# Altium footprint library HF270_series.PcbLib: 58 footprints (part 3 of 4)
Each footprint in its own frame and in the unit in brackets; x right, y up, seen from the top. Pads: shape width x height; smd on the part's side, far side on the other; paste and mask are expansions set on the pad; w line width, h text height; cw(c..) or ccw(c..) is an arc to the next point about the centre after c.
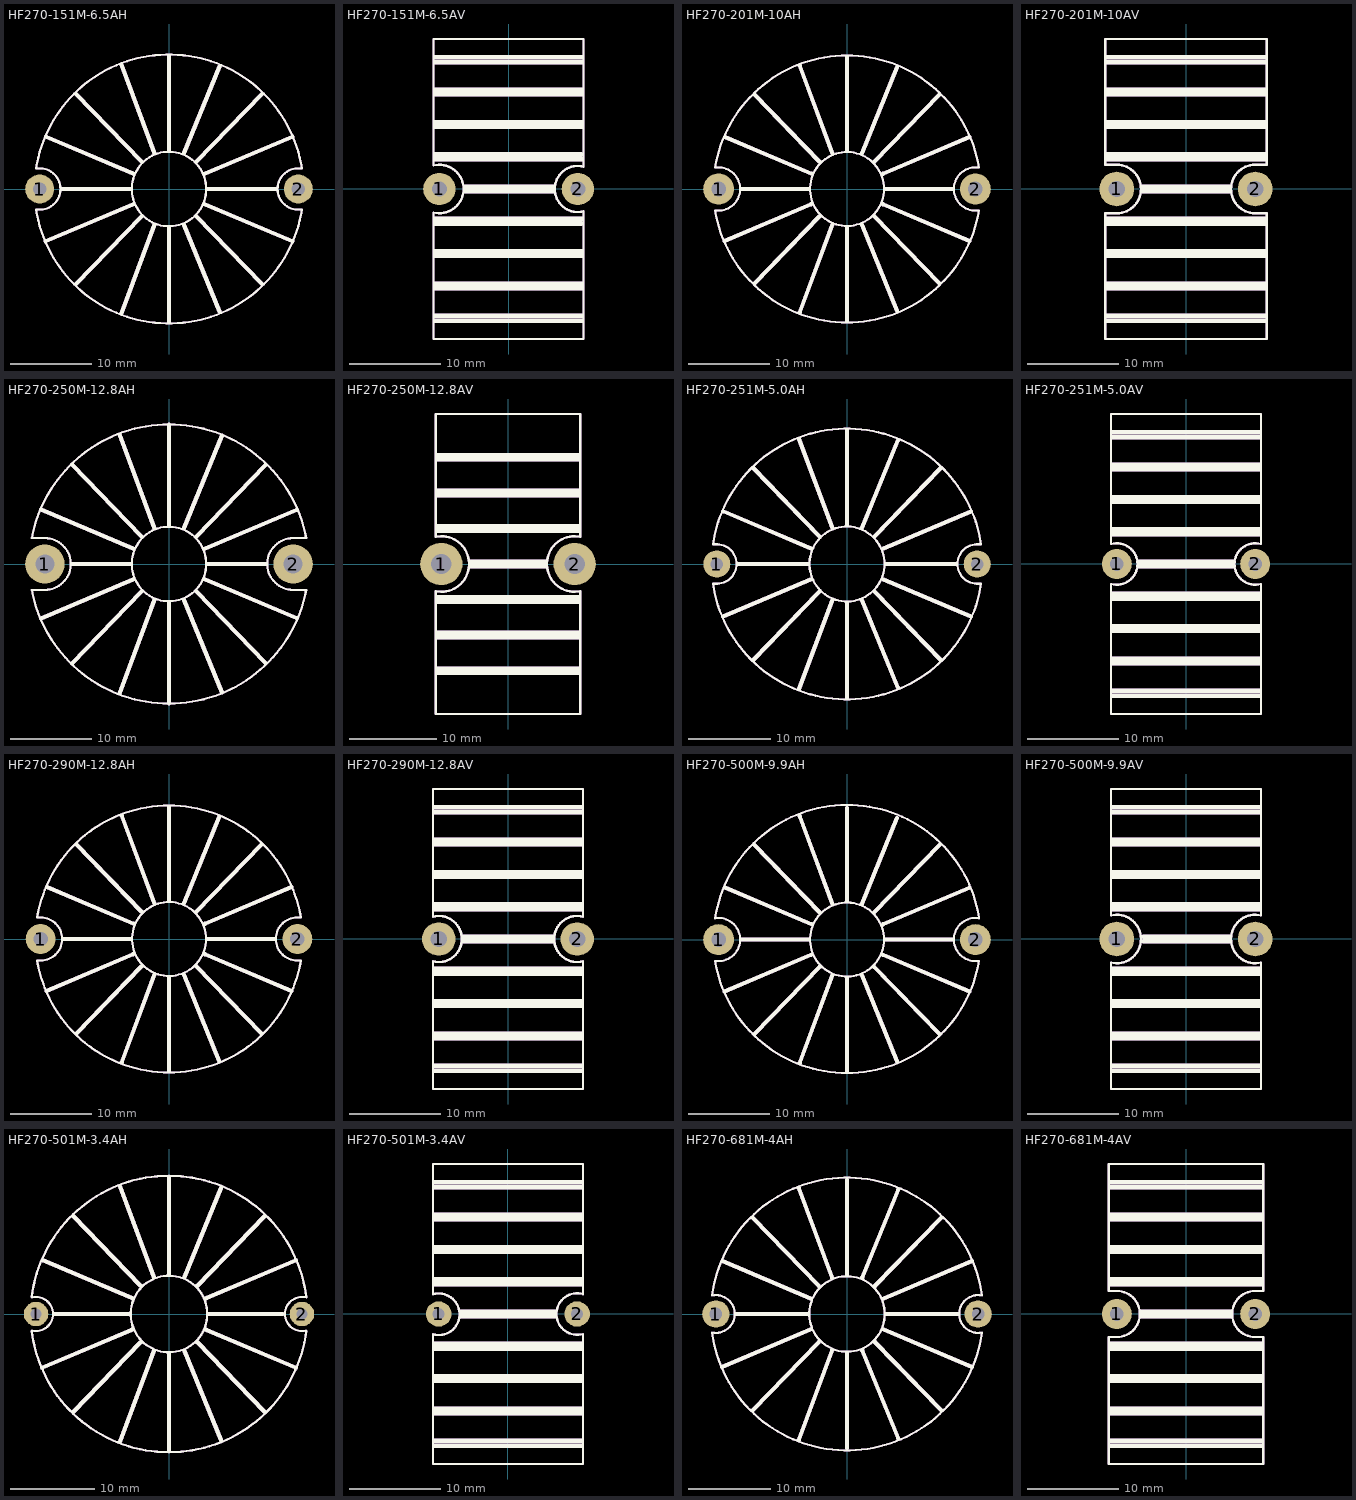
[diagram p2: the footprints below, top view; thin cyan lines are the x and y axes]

## HF270-151M-6.5AH [mil]
pads (2):
  round 140 hole 65: 1(-625,0) 2(625,0)
Top Overlay:
  circle w10: c0,0 r180
  lines w10: -642.5,-98.46 ccw(c0,0) 642.5,-98.46 cw(c625,0) 642.5,98.46 ccw(c0,0) -642.5,98.46 cw(c-625,0) -642.5,-98.46
  lines w19.68: -596.03,-252.56 -175.3,-74.28 ; -593.79,252.95 -173.05,74.68 ; -520,0 -185,0 ; -450,-460 -132.7,-132.43 ; -450,460 -132.7,132.43 ; -230,-600 -70.44,-171.87 ; -230,600 -70.44,171.87 ; 0,-640 0,-185 ; 0,185 0,640 ; 72.46,-173.99 243.97,-592.47 ; 72.46,173.99 243.97,592.47 ; 132.5,-132.5 450,-460 ; 132.5,132.5 450,460 ; 175.3,-74.28 596.03,-252.56 ; 175.3,74.28 596.03,252.56 ; 185,0 520,0
Mechanical 29:
  circle w10: c0,0 r180
  lines w10: -642.5,-98.46 ccw(c0,0) 642.5,-98.46 cw(c625,0) 642.5,98.46 ccw(c0,0) -642.5,98.46 cw(c-625,0) -642.5,-98.46
  lines w19.68: -596.03,-252.56 -175.3,-74.28 ; -593.79,252.95 -173.05,74.68 ; -520,0 -185,0 ; -450,-460 -132.7,-132.43 ; -450,460 -132.7,132.43 ; -230,-600 -70.44,-171.87 ; -230,600 -70.44,171.87 ; 0,-640 0,-185 ; 0,185 0,640 ; 72.46,-173.99 243.97,-592.47 ; 72.46,173.99 243.97,592.47 ; 132.5,-132.5 450,-460 ; 132.5,132.5 450,460 ; 175.3,-74.28 596.03,-252.56 ; 175.3,74.28 596.03,252.56 ; 185,0 520,0
  text "'.Designator'" at -290,145.15 h400

## HF270-151M-6.5AV [mil]
pads (2):
  round 140 hole 65: 1(-300,0) 2(300,0)
Top Overlay:
  lines w10: -325,-650 325,-650 325,-96.82 cw(c300,0) 325,96.82 325,650 -325,650 -325,101.98 cw(c-300,0) -325,-101.98 -325,-650
  lines w19.68: -320,-570 320,-570 ; -320,-550 320,-550 ; -320,-430 320,-430 ; -320,-410 320,-410 ; -320,-290 320,-290 ; -320,-270 320,-270 ; -320,-150 315,-150 ; -320,-130 320,-130 ; -320,130 320,130 ; -320,150 315,150 ; -320,270 320,270 ; -320,290 320,290 ; -320,410 320,410 ; -320,430 320,430 ; -320,550 320,550 ; -320,570 320,570 ; -190,-10 195,-10 ; -190,10 195,10
Mechanical 29:
  lines w10: -325,-650 325,-650 325,-96.82 cw(c300,0) 325,96.82 325,650 -325,650 -325,101.98 cw(c-300,0) -325,-101.98 -325,-650
  lines w19.68: -320,-570 320,-570 ; -320,-550 320,-550 ; -320,-430 320,-430 ; -320,-410 320,-410 ; -320,-290 320,-290 ; -320,-270 320,-270 ; -320,-150 315,-150 ; -320,-130 320,-130 ; -320,130 320,130 ; -320,150 315,150 ; -320,270 320,270 ; -320,290 320,290 ; -320,410 320,410 ; -320,430 320,430 ; -320,550 320,550 ; -320,570 320,570 ; -190,-10 195,-10 ; -190,10 195,10
  text "'.Designator'" at -1750,-64.85 h400

## HF270-201M-10AH [mil]
pads (2):
  round 150 hole 71: 1(-625,0) 2(625,0)
Top Overlay:
  circle w10: c0,0 r180
  lines w10: -641.68,-103.67 ccw(c0,0) 641.68,-103.67 cw(c625,0) 641.68,103.67 ccw(c0,0) -641.68,103.67 cw(c-625,0) -641.68,-103.67
  lines w19.68: -596.03,-252.56 -175.3,-74.28 ; -593.79,252.95 -173.05,74.68 ; -515,0 -185,0 ; -450,-460 -132.7,-132.43 ; -450,460 -132.7,132.43 ; -230,-600 -70.44,-171.87 ; -230,600 -70.44,171.87 ; 0,-640 0,-185 ; 0,185 0,640 ; 72.46,-173.99 243.97,-592.47 ; 72.46,173.99 243.97,592.47 ; 132.5,-132.5 450,-460 ; 132.5,132.5 450,460 ; 175.3,-74.28 596.03,-252.56 ; 175.3,74.28 596.03,252.56 ; 185,0 515,0
Mechanical 29:
  circle w10: c0,0 r180
  lines w10: -641.68,-103.67 ccw(c0,0) 641.68,-103.67 cw(c625,0) 641.68,103.67 ccw(c0,0) -641.68,103.67 cw(c-625,0) -641.68,-103.67
  lines w19.68: -596.03,-252.56 -175.3,-74.28 ; -593.79,252.95 -173.05,74.68 ; -515,0 -185,0 ; -450,-460 -132.7,-132.43 ; -450,460 -132.7,132.43 ; -230,-600 -70.44,-171.87 ; -230,600 -70.44,171.87 ; 0,-640 0,-185 ; 0,185 0,640 ; 72.46,-173.99 243.97,-592.47 ; 72.46,173.99 243.97,592.47 ; 132.5,-132.5 450,-460 ; 132.5,132.5 450,460 ; 175.3,-74.28 596.03,-252.56 ; 175.3,74.28 596.03,252.56 ; 185,0 515,0
  text "'.Designator'" at -290,145.15 h400

## HF270-201M-10AV [mil]
pads (2):
  round 150 hole 71: 1(-300,0) 2(300,0)
Top Overlay:
  lines w10: -350,-650 350,-650 350,-105 300,-105 cw(c300,0) 300,105 350,105 350,650 -350,650 -350,105 -300,105 cw(c-300,0) -300,-105 -350,-105 -350,-650
  lines w19.68: -345,-570 345,-570 ; -345,-550 345,-550 ; -345,-430 345,-430 ; -345,-410 345,-410 ; -345,-290 345,-290 ; -345,-270 345,-270 ; -345,-150 345,-150 ; -345,-130 345,-130 ; -345,130 345,130 ; -345,150 345,150 ; -345,270 345,270 ; -345,290 345,290 ; -345,410 345,410 ; -345,430 345,430 ; -345,550 345,550 ; -345,570 345,570 ; -190,-10 190,-10 ; -190,10 190,10
Mechanical 29:
  lines w10: -350,-650 350,-650 350,-105 300,-105 cw(c300,0) 300,105 350,105 350,650 -350,650 -350,105 -300,105 cw(c-300,0) -300,-105 -350,-105 -350,-650
  lines w19.68: -345,-570 345,-570 ; -345,-550 345,-550 ; -345,-430 345,-430 ; -345,-410 345,-410 ; -345,-290 345,-290 ; -345,-270 345,-270 ; -345,-150 345,-150 ; -345,-130 345,-130 ; -345,130 345,130 ; -345,150 345,150 ; -345,270 345,270 ; -345,290 345,290 ; -345,410 345,410 ; -345,430 345,430 ; -345,550 345,550 ; -345,570 345,570 ; -190,-10 190,-10 ; -190,10 190,10
  text "'.Designator'" at -1750,-64.85 h400

## HF270-250M-12.8AH [mil]
pads (2):
  round 190 hole 91: 1(-600,0) 2(600,0)
Top Overlay:
  circle w10: c0,0 r180
  lines w10: -663.21,-125.61 ccw(c0,0) 663.32,-125.02 ; -663.21,-125 -600,-125 ccw(c-600,0) -600,125 -663.21,125 ; -663.21,125.61 cw(c0,0) 663.32,125.02 ; 663.21,-125 600,-125 cw(c600,0) 600,125 663.21,125
  lines w19.68: -618.54,-263.44 -173.05,-74.68 ; -618.54,263.44 -173.05,74.68 ; -470,0 -185,0 ; -469.6,-480.23 -132.7,-132.43 ; -469.6,480.23 -132.7,132.43 ; -240.01,-626.86 -70.44,-171.87 ; -240.01,626.86 -70.44,171.87 ; 0,-675 0,-185 ; 0,185 0,675 ; 72.46,-173.99 255.93,-621.67 ; 72.46,173.99 255.93,621.67 ; 132.5,-132.5 467.26,-477.81 ; 132.5,132.5 467.26,477.81 ; 175.3,-74.28 619.03,-262.3 ; 175.3,74.28 619.03,262.3 ; 185,0 470,0
Mechanical 29:
  circle w10: c0,0 r180
  lines w10: -663.21,-125.61 ccw(c0,0) 663.32,-125.02 ; -663.21,-125 -600,-125 ccw(c-600,0) -600,125 -663.21,125 ; -663.21,125.61 cw(c0,0) 663.32,125.02 ; 663.21,-125 600,-125 cw(c600,0) 600,125 663.21,125
  lines w19.68: -618.54,-263.44 -173.05,-74.68 ; -618.54,263.44 -173.05,74.68 ; -470,0 -185,0 ; -469.6,-480.23 -132.7,-132.43 ; -469.6,480.23 -132.7,132.43 ; -240.01,-626.86 -70.44,-171.87 ; -240.01,626.86 -70.44,171.87 ; 0,-675 0,-185 ; 0,185 0,675 ; 72.46,-173.99 255.93,-621.67 ; 72.46,173.99 255.93,621.67 ; 132.5,-132.5 467.26,-477.81 ; 132.5,132.5 467.26,477.81 ; 175.3,-74.28 619.03,-262.3 ; 175.3,74.28 619.03,262.3 ; 185,0 470,0
  text "'.Designator'" at -290,145.15 h400

## HF270-250M-12.8AV [mil]
pads (2):
  round 190 hole 91: 1(-300,0) 2(300,0)
Top Overlay:
  lines w10: -325,-675 325,-675 325,-122.47 cw(c300,0) 325,122.47 325,675 -325,675 -325,122.47 cw(c-300,0) -325,-122.47 -325,-675
  lines w19.68: -320,-490 320,-490 ; -320,-470 320,-470 ; -320,-330 320,-330 ; -320,-310 320,-310 ; -320,-170 320,-170 ; -320,-150 320,-150 ; -320,150 320,150 ; -320,170 320,170 ; -320,310 320,310 ; -320,330 320,330 ; -320,470 320,470 ; -320,490 320,490 ; -170,-10 170,-10 ; -170,10 170,10
Mechanical 29:
  lines w10: -325,-675 325,-675 325,-122.47 cw(c300,0) 325,122.47 325,675 -325,675 -325,122.47 cw(c-300,0) -325,-122.47 -325,-675
  lines w19.68: -320,-490 320,-490 ; -320,-470 320,-470 ; -320,-330 320,-330 ; -320,-310 320,-310 ; -320,-170 320,-170 ; -320,-150 320,-150 ; -320,150 320,150 ; -320,170 320,170 ; -320,310 320,310 ; -320,330 320,330 ; -320,470 320,470 ; -320,490 320,490 ; -170,-10 170,-10 ; -170,10 170,10
  text "'.Designator'" at -1750,-64.85 h400

## HF270-251M-5.0AH [mil]
pads (2):
  round 130 hole 60: 1(-625,0) 2(625,0)
Top Overlay:
  circle w10: c0,0 r180
  lines w10: -643.28,-93.22 ccw(c-625,0) -643.28,93.22 cw(c0,0) 643.28,93.22 ccw(c625,0) 643.28,-93.22 cw(c0,0) -643.28,-93.22
  lines w19.68: -596.03,-252.56 -175.3,-74.28 ; -593.79,252.95 -173.05,74.68 ; -525,0 -185,0 ; -450,-460 -132.7,-132.43 ; -450,460 -132.7,132.43 ; -230,-600 -70.44,-171.87 ; -230,600 -70.44,171.87 ; 0,-640 0,-185 ; 0,185 0,640 ; 72.46,-173.99 243.97,-592.47 ; 72.46,173.99 243.97,592.47 ; 132.5,-132.5 450,-460 ; 132.5,132.5 450,460 ; 175.3,-74.28 596.03,-252.56 ; 175.3,74.28 596.03,252.56 ; 185,0 525,0
Mechanical 29:
  circle w10: c0,0 r180
  lines w10: -643.28,-93.22 ccw(c-625,0) -643.28,93.22 cw(c0,0) 643.28,93.22 ccw(c625,0) 643.28,-93.22 cw(c0,0) -643.28,-93.22
  lines w19.68: -596.03,-252.56 -175.3,-74.28 ; -593.79,252.95 -173.05,74.68 ; -525,0 -185,0 ; -450,-460 -132.7,-132.43 ; -450,460 -132.7,132.43 ; -230,-600 -70.44,-171.87 ; -230,600 -70.44,171.87 ; 0,-640 0,-185 ; 0,185 0,640 ; 72.46,-173.99 243.97,-592.47 ; 72.46,173.99 243.97,592.47 ; 132.5,-132.5 450,-460 ; 132.5,132.5 450,460 ; 175.3,-74.28 596.03,-252.56 ; 175.3,74.28 596.03,252.56 ; 185,0 525,0
  text "'.Designator'" at -290,145.15 h400

## HF270-251M-5.0AV [mil]
pads (2):
  round 130 hole 60: 1(-300,0) 2(300,0)
Top Overlay:
  lines w10: -325,-86.72 -325,-650 325,-650 325,-86.72 ; -325,86.72 -325,650 325,650 325,86.72 ; -324.09,-86.72 ccw(c-300,0) -324.09,86.72 ; 324.09,-86.72 cw(c300,0) 324.09,86.72
  lines w19.68: -320,-570 320,-570 ; -320,-550 320,-550 ; -320,-430 320,-430 ; -320,-410 320,-410 ; -320,-290 320,-290 ; -320,-270 320,-270 ; -320,-150 320,-150 ; -320,-130 320,-130 ; -320,130 320,130 ; -320,150 320,150 ; -320,270 320,270 ; -320,290 320,290 ; -320,410 320,410 ; -320,430 320,430 ; -320,550 320,550 ; -320,570 320,570 ; -205,-10 205,-10 ; -205,10 205,10
Mechanical 29:
  lines w10: -325,-86.72 -325,-650 325,-650 325,-86.72 ; -325,86.72 -325,650 325,650 325,86.72 ; -324.09,-86.72 ccw(c-300,0) -324.09,86.72 ; 324.09,-86.72 cw(c300,0) 324.09,86.72
  lines w19.68: -320,-570 320,-570 ; -320,-550 320,-550 ; -320,-430 320,-430 ; -320,-410 320,-410 ; -320,-290 320,-290 ; -320,-270 320,-270 ; -320,-150 320,-150 ; -320,-130 320,-130 ; -320,130 320,130 ; -320,150 320,150 ; -320,270 320,270 ; -320,290 320,290 ; -320,410 320,410 ; -320,430 320,430 ; -320,550 320,550 ; -320,570 320,570 ; -205,-10 205,-10 ; -205,10 205,10
  text "'.Designator'" at -1750,-64.85 h400

## HF270-290M-12.8AH [mil]
pads (2):
  round 145 hole 70: 1(-625,0) 2(625,0)
Top Overlay:
  circle w10: c0,0 r180
  lines w10: -641.43,-105.18 ccw(c0,0) 641.43,-105.18 ; -641.43,105.18 cw(c0,0) 641.43,105.18 ; -640.35,-105 -625,-105 ccw(c-625,0) -625,105 -640.35,105 ; 640.35,-105 625,-105 cw(c625,0) 625,105 640.35,105
  lines w19.68: -596.03,-252.56 -175.3,-74.28 ; -593.79,252.95 -173.05,74.68 ; -515,0 -185,0 ; -450,-460 -132.7,-132.43 ; -450,460 -132.7,132.43 ; -230,-600 -70.44,-171.87 ; -230,600 -70.44,171.87 ; 0,-640 0,-185 ; 0,185 0,640 ; 72.46,-173.99 243.97,-592.47 ; 72.46,173.99 243.97,592.47 ; 132.5,-132.5 450,-460 ; 132.5,132.5 450,460 ; 175.3,-74.28 596.03,-252.56 ; 175.3,74.28 596.03,252.56 ; 185,0 515,0
Mechanical 29:
  circle w10: c0,0 r180
  lines w10: -641.43,-105.18 ccw(c0,0) 641.43,-105.18 ; -641.43,105.18 cw(c0,0) 641.43,105.18 ; -640.35,-105 -625,-105 ccw(c-625,0) -625,105 -640.35,105 ; 640.35,-105 625,-105 cw(c625,0) 625,105 640.35,105
  lines w19.68: -596.03,-252.56 -175.3,-74.28 ; -593.79,252.95 -173.05,74.68 ; -515,0 -185,0 ; -450,-460 -132.7,-132.43 ; -450,460 -132.7,132.43 ; -230,-600 -70.44,-171.87 ; -230,600 -70.44,171.87 ; 0,-640 0,-185 ; 0,185 0,640 ; 72.46,-173.99 243.97,-592.47 ; 72.46,173.99 243.97,592.47 ; 132.5,-132.5 450,-460 ; 132.5,132.5 450,460 ; 175.3,-74.28 596.03,-252.56 ; 175.3,74.28 596.03,252.56 ; 185,0 515,0
  text "'.Designator'" at -290,145.15 h400

## HF270-290M-12.8AV [mil]
pads (2):
  round 145 hole 70: 1(-300,0) 2(300,0)
Top Overlay:
  lines w10: -325,-650 325,-650 325,-96.82 cw(c300,0) 325,96.82 325,650 -325,650 -325,96.82 cw(c-300,0) -325,-96.82 -325,-650
  lines w19.68: -320,-570 320,-570 ; -320,-550 320,-550 ; -320,-430 320,-430 ; -320,-410 320,-410 ; -320,-290 320,-290 ; -320,-270 320,-270 ; -320,-150 320,-150 ; -320,-130 320,-130 ; -320,130 320,130 ; -320,150 320,150 ; -320,270 320,270 ; -320,290 320,290 ; -320,410 320,410 ; -320,430 320,430 ; -320,550 320,550 ; -320,570 320,570 ; -195,-10 195,-10 ; -195,10 195,10
Mechanical 29:
  lines w10: -325,-650 325,-650 325,-96.82 cw(c300,0) 325,96.82 325,650 -325,650 -325,96.82 cw(c-300,0) -325,-96.82 -325,-650
  lines w19.68: -320,-570 320,-570 ; -320,-550 320,-550 ; -320,-430 320,-430 ; -320,-410 320,-410 ; -320,-290 320,-290 ; -320,-270 320,-270 ; -320,-150 320,-150 ; -320,-130 320,-130 ; -320,150 320,150 ; -320,270 320,270 ; -320,290 320,290 ; -320,410 320,410 ; -320,430 320,430 ; -320,550 320,550 ; -320,570 320,570 ; -195,-10 195,-10 ; -195,10 195,10 ; -320,130 320,130 -320,130
  text "'.Designator'" at -1750,-64.85 h400

## HF270-500M-9.9AH [mil]
pads (2):
  round 150 hole 71: 1(-625,0) 2(625,0)
Top Overlay:
  circle w10: c0,0 r180
  lines w10: 641.68,103.67 ccw(c625,0) 641.68,-103.67 cw(c0,0) -641.68,-103.67 ccw(c-625,0) -641.68,103.67 cw(c0.82,5.21) 642.5,108.88
  lines w19.68: -596.03,-252.56 -175.3,-74.28 ; -593.79,252.95 -173.05,74.68 ; -515,0 -185,0 ; -450,-460 -132.7,-132.43 ; -450,460 -132.7,132.43 ; -230,-600 -70.44,-171.87 ; -230,600 -70.44,171.87 ; 0,-640 0,-185 ; 0,185 0,640 ; 72.46,-173.99 243.97,-592.47 ; 72.46,173.99 243.97,592.47 ; 132.5,-132.5 450,-460 ; 132.5,132.5 450,460 ; 175.3,-74.28 596.03,-252.56 ; 175.3,74.28 596.03,252.56 ; 185,0 515,0
Mechanical 29:
  circle w10: c0,0 r180
  lines w10: 641.68,103.67 ccw(c625,0) 641.68,-103.67 cw(c0,0) -641.68,-103.67 ccw(c-625,0) -641.68,103.67 cw(c0.82,5.21) 642.5,108.88
  lines w19.68: -596.03,-252.56 -175.3,-74.28 ; -593.79,252.95 -173.05,74.68 ; -515,0 -185,0 ; -450,-460 -132.7,-132.43 ; -450,460 -132.7,132.43 ; -230,-600 -70.44,-171.87 ; -230,600 -70.44,171.87 ; 0,-640 0,-185 ; 0,185 0,640 ; 72.46,-173.99 243.97,-592.47 ; 72.46,173.99 243.97,592.47 ; 132.5,-132.5 450,-460 ; 132.5,132.5 450,460 ; 175.3,-74.28 596.03,-252.56 ; 175.3,74.28 596.03,252.56 ; 185,0 515,0
  text "'.Designator'" at -290,145.15 h400

## HF270-500M-9.9AV [mil]
pads (2):
  round 150 hole 71: 1(-300,0) 2(300,0)
Top Overlay:
  lines w10: -325,-102.25 -325,-650 325,-650 325,-102.25 ; -325,102.22 -325,650 325,650 325,102.22 ; -323.99,102.22 cw(c-300,0) -323.86,-102.25 ; 323.86,-102.25 cw(c300,0) 323.99,102.22
  lines w19.68: -320,-570 320,-570 ; -320,-550 320,-550 ; -320,-430 320,-430 ; -320,-410 320,-410 ; -320,-290 320,-290 ; -320,-270 320,-270 ; -320,-150 320,-150 ; -320,-130 320,-130 ; -320,130 320,130 ; -320,150 320,150 ; -320,270 320,270 ; -320,290 320,290 ; -320,410 320,410 ; -320,430 320,430 ; -320,550 320,550 ; -320,570 320,570 ; -185,-10 190,-10 ; -185,10 190,10
Mechanical 29:
  lines w10: -325,-102.25 -325,-650 325,-650 325,-102.25 ; -325,102.22 -325,650 325,650 325,102.22 ; -323.99,102.22 cw(c-300,0) -323.86,-102.25 ; 323.86,-102.25 cw(c300,0) 323.99,102.22
  lines w19.68: -320,-570 320,-570 ; -320,-550 320,-550 ; -320,-430 320,-430 ; -320,-410 320,-410 ; -320,-290 320,-290 ; -320,-270 320,-270 ; -320,-150 320,-150 ; -320,-130 320,-130 ; -320,130 320,130 ; -320,150 320,150 ; -320,270 320,270 ; -320,290 320,290 ; -320,410 320,410 ; -320,430 320,430 ; -320,550 320,550 ; -320,570 320,570 ; -185,-10 190,-10 ; -185,10 190,10
  text "'.Designator'" at -1750,-64.85 h400

## HF270-501M-3.4AH [mil]
pads (2):
  round 115 hole 52: 1(-625,0) 2(625,0)
Top Overlay:
  circle w10: c0,0 r180
  lines w10: -644.98,-80.62 ccw(c0,0) 645.06,-80.01 ; -644.9,81.25 cw(c0,0) 644.98,80.62 ; -644.4,-77.61 ccw(c-625,0) -644.4,77.61 ; 644.4,-77.61 cw(c625,0) 645.61,77.3
  lines w19.68: -596.03,-252.56 -175.3,-74.28 ; -593.79,252.95 -173.05,74.68 ; -540,0 -185,0 ; -450,-460 -132.7,-132.43 ; -450,460 -132.7,132.43 ; -230,-600 -70.44,-171.87 ; -230,600 -70.44,171.87 ; 0,-640 0,-185 ; 0,185 0,640 ; 72.46,-173.99 243.97,-592.47 ; 72.46,173.99 243.97,592.47 ; 132.5,-132.5 450,-460 ; 132.5,132.5 450,460 ; 175.3,-74.28 596.03,-252.56 ; 175.3,74.28 596.03,252.56 ; 185,0 535,0
Mechanical 29:
  circle w10: c0,0 r180
  lines w10: -644.98,-80.62 ccw(c0,0) 645.06,-80.01 ; -644.9,81.25 cw(c0,0) 644.98,80.62 ; -644.4,-77.61 ccw(c-625,0) -644.4,77.61 ; 644.4,-77.61 cw(c625,0) 645.61,77.3
  lines w19.68: -596.03,-252.56 -175.3,-74.28 ; -593.79,252.95 -173.05,74.68 ; -540,0 -185,0 ; -450,-460 -132.7,-132.43 ; -450,460 -132.7,132.43 ; -230,-600 -70.44,-171.87 ; -230,600 -70.44,171.87 ; 0,-640 0,-185 ; 0,185 0,640 ; 72.46,-173.99 243.97,-592.47 ; 72.46,173.99 243.97,592.47 ; 132.5,-132.5 450,-460 ; 132.5,132.5 450,460 ; 175.3,-74.28 596.03,-252.56 ; 175.3,74.28 596.03,252.56 ; 185,0 535,0
  text "'.Designator'" at -290,145.15 h400

## HF270-501M-3.4AV [mil]
pads (2):
  round 110 hole 52: 1(-300,0) 2(300,0)
Top Overlay:
  lines w10: -325,84.12 -325,650 325,650 325,85.49 ; -325,84.97 cw(c-299.6,-1.37) -325,-87.71 -325,-650 325,-650 325,-86.46 cw(c300,0) 325,86.46
  lines w19.68: -320,-570 320,-570 ; -320,-550 320,-550 ; -320,-430 320,-430 ; -320,-410 320,-410 ; -320,-290 320,-290 ; -320,-270 320,-270 ; -320,-150 320,-150 ; -320,-130 320,-130 ; -320,130 320,130 ; -320,150 320,150 ; -320,270 320,270 ; -320,290 320,290 ; -320,410 320,410 ; -320,430 320,430 ; -320,550 320,550 ; -320,570 320,570 ; -205,-10 205,-10 ; -205,10 205,10
Mechanical 29:
  lines w10: -325,84.12 -325,650 325,650 325,85.49 ; -325,84.97 cw(c-299.6,-1.37) -325,-87.71 -325,-650 325,-650 325,-86.46 cw(c300,0) 325,86.46
  lines w19.68: -320,-570 320,-570 ; -320,-550 320,-550 ; -320,-430 320,-430 ; -320,-410 320,-410 ; -320,-290 320,-290 ; -320,-270 320,-270 ; -320,-150 320,-150 ; -320,-130 320,-130 ; -320,130 320,130 ; -320,150 320,150 ; -320,270 320,270 ; -320,290 320,290 ; -320,410 320,410 ; -320,430 320,430 ; -320,550 320,550 ; -320,570 320,570 ; -205,-10 205,-10 ; -205,10 205,10
  text "'.Designator'" at -1750,-64.85 h400

## HF270-681M-4AH [mil]
pads (2):
  round 130 hole 60: 1(-625,0) 2(625,0)
Top Overlay:
  circle w10: c0,0 r180
  lines w10: -644.02,-87.97 ccw(c-625,0) -644.02,87.97 cw(c0,0) 644.02,87.97 ccw(c625,0) 644.02,-87.97 cw(c0,0) -644.02,-87.97
  lines w19.68: -596.03,-252.56 -175.3,-74.28 ; -593.79,252.95 -173.05,74.68 ; -530,0 -185,0 ; -450,-460 -132.7,-132.43 ; -450,460 -132.7,132.43 ; -230,-600 -70.44,-171.87 ; -230,600 -70.44,171.87 ; 0,-640 0,-185 ; 0,185 0,640 ; 72.46,-173.99 243.97,-592.47 ; 72.46,173.99 243.97,592.47 ; 132.5,-132.5 450,-460 ; 132.5,132.5 450,460 ; 175.3,-74.28 596.03,-252.56 ; 175.3,74.28 596.03,252.56 ; 185,0 530,0
Mechanical 29:
  circle w10: c0,0 r180
  lines w10: -644.02,-87.97 ccw(c-625,0) -644.02,87.97 cw(c0,0) 644.02,87.97 ccw(c625,0) 644.02,-87.97 cw(c0,0) -644.02,-87.97
  lines w19.68: -596.03,-252.56 -175.3,-74.28 ; -593.79,252.95 -173.05,74.68 ; -530,0 -185,0 ; -450,-460 -132.7,-132.43 ; -450,460 -132.7,132.43 ; -230,-600 -70.44,-171.87 ; -230,600 -70.44,171.87 ; 0,-640 0,-185 ; 0,185 0,640 ; 72.46,-173.99 243.97,-592.47 ; 72.46,173.99 243.97,592.47 ; 132.5,-132.5 450,-460 ; 132.5,132.5 450,460 ; 175.3,-74.28 596.03,-252.56 ; 175.3,74.28 596.03,252.56 ; 185,0 530,0
  text "'.Designator'" at -290,145.15 h400

## HF270-681M-4AV [mil]
pads (2):
  round 130 hole 60: 1(-300,0) 2(300,0)
Top Overlay:
  lines w10: -335,-650 -335,-100 -300,-100 ccw(c-300,0) -300,100 -335,100 -335,650 335,650 335,100 300,100 ccw(c300,0) 300,-100 335,-100 335,-650 -335,-650
  lines w19.68: -330,-570 330,-570 ; -330,-550 330,-550 ; -330,-430 330,-430 ; -330,-410 330,-410 ; -330,-290 330,-290 ; -330,-270 330,-270 ; -330,-150 330,-150 ; -330,-130 330,-130 ; -330,130 330,130 ; -330,150 330,150 ; -330,270 330,270 ; -330,290 330,290 ; -330,410 330,410 ; -330,430 330,430 ; -330,550 330,550 ; -330,570 330,570 ; -195,-10 195,-10 ; -195,10 195,10
Mechanical 29:
  lines w10: -335,-650 -335,-100 -300,-100 ccw(c-300,0) -300,100 -335,100 -335,650 335,650 335,100 300,100 ccw(c300,0) 300,-100 335,-100 335,-650 -335,-650
  lines w19.68: -330,-570 330,-570 ; -330,-550 330,-550 ; -330,-430 330,-430 ; -330,-410 330,-410 ; -330,-290 330,-290 ; -330,-270 330,-270 ; -330,-150 330,-150 ; -330,-130 330,-130 ; -330,130 330,130 ; -330,150 330,150 ; -330,270 330,270 ; -330,290 330,290 ; -330,410 330,410 ; -330,430 330,430 ; -330,550 330,550 ; -330,570 330,570 ; -195,-10 195,-10 ; -195,10 195,10
  text "'.Designator'" at -1750,-64.85 h400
